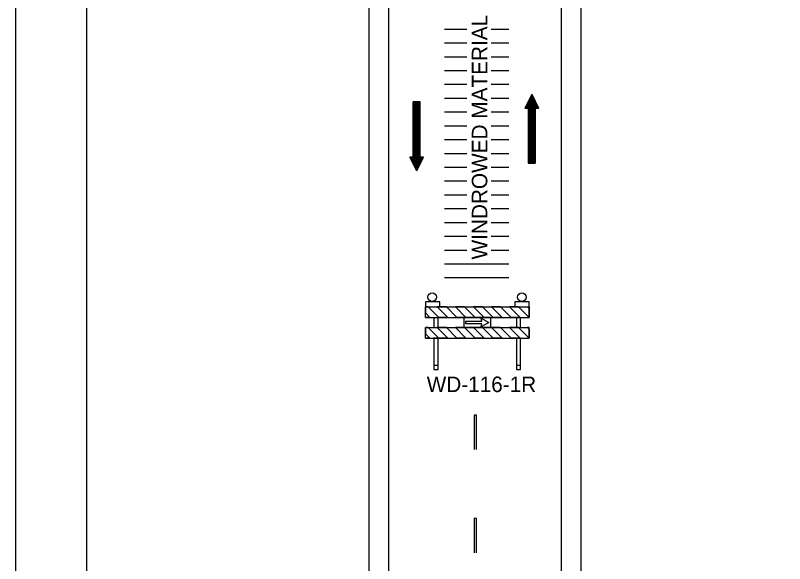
# Model space of a CAD drawing. Extents: x 797 to 1013, y 120 to 399.
# Drawn here: x 797.2 to 905.2, y 193.1 to 270.1 of the extents above; entities that cross this region are included whole.
import ezdxf

# ---------------------------------------------------------------- set-up
doc = ezdxf.new("R2010")
doc.units = 0
for name, color, linetype in [('Level 10', 7, 'Continuous'), ('Level 2', 7, 'Continuous'), ('Level 5', 7, 'Continuous'), ('Level 60', 7, 'Continuous')]:
    doc.layers.add(name, color=color, linetype=linetype)

msp = doc.modelspace()

# ---------------------------------------------------------------- linework, layer by layer
at = {"layer": 'Level 10'}
for p, q in [((846.78, 383.98), (846.78, 135.76)), ((849.54, 383.98), (849.54, 135.76)), ((873.78, 383.98), (873.78, 135.76)), ((876.53, 383.98), (876.53, 135.76)), ((857.39, 268.16), (860.54, 268.16)), ((863.97, 268.16), (866.43, 268.16)), ((857.39, 266.22), (860.54, 266.22)), ((863.97, 266.22), (866.43, 266.22)), ((857.39, 264.28), (860.54, 264.28)), ((863.97, 264.28), (866.43, 264.28)), ((849.54, 262.25), (849.55, 262.24)), ((857.39, 262.34), (860.54, 262.34)), ((863.97, 262.34), (866.43, 262.34)), ((857.39, 260.4), (860.54, 260.4)), ((863.97, 260.4), (866.43, 260.4)), ((857.39, 258.46), (860.54, 258.46)), ((863.97, 258.46), (866.43, 258.46)), ((869.65, 259.01), (868.68, 257.07)), ((869.29, 258.28), (869.29, 249.31)), ((869.41, 258.52), (869.41, 249.31)), ((869.53, 258.77), (869.53, 249.31)), ((869.65, 259.01), (869.65, 249.31)), ((869.65, 259.01), (870.62, 257.07)), ((869.77, 258.77), (869.77, 249.31)), ((869.89, 258.52), (869.89, 249.31)), ((870.01, 258.28), (870.01, 249.31)), ((853.03, 250.17), (853.03, 257.93)), ((854, 257.93), (853.03, 257.93)), ((853.03, 249.2), (853.03, 257.93)), ((853.15, 248.96), (853.15, 257.93)), ((853.27, 248.72), (853.27, 257.93)), ((853.39, 248.47), (853.39, 257.93)), ((853.51, 248.23), (853.51, 257.93)), ((853.63, 248.47), (853.63, 257.93)), ((853.75, 248.72), (853.75, 257.93)), ((853.88, 248.96), (853.88, 257.93)), ((854, 250.17), (854, 257.93)), ((854, 249.2), (854, 257.93)), ((868.68, 257.07), (869.17, 257.07)), ((868.8, 257.31), (868.8, 257.07)), ((868.92, 257.55), (868.92, 257.07)), ((869.05, 257.8), (869.05, 257.07)), ((869.17, 258.04), (869.17, 249.31)), ((869.17, 257.07), (869.17, 249.31)), ((870.14, 258.04), (870.14, 249.31)), ((870.14, 257.07), (870.14, 249.31)), ((870.14, 257.07), (870.62, 257.07)), ((870.26, 257.8), (870.26, 257.07)), ((870.38, 257.55), (870.38, 257.07)), ((870.5, 257.31), (870.5, 257.07)), ((857.39, 256.52), (860.54, 256.52)), ((863.97, 256.52), (866.43, 256.52)), ((857.39, 254.58), (860.54, 254.58)), ((863.97, 254.58), (866.43, 254.58)), ((857.39, 252.64), (860.54, 252.64)), ((863.97, 252.64), (866.43, 252.64)), ((857.39, 250.7), (860.54, 250.7)), ((863.97, 250.7), (866.43, 250.7)), ((853.51, 248.23), (852.54, 250.17)), ((853.03, 250.17), (852.54, 250.17)), ((852.66, 249.93), (852.66, 250.17)), ((852.78, 249.69), (852.78, 250.17)), ((852.9, 249.44), (852.9, 250.17)), ((853.51, 248.23), (854.48, 250.17)), ((854.48, 250.17), (854, 250.17)), ((854.12, 249.44), (854.12, 250.17)), ((854.24, 249.69), (854.24, 250.17)), ((854.36, 249.93), (854.36, 250.17)), ((857.39, 248.76), (860.54, 248.76)), ((863.97, 248.76), (866.43, 248.76)), ((869.17, 249.31), (870.14, 249.31)), ((857.39, 246.83), (860.54, 246.83)), ((863.97, 246.83), (866.43, 246.83)), ((857.39, 244.89), (860.54, 244.89)), ((863.97, 244.89), (866.43, 244.89)), ((857.39, 242.95), (860.54, 242.95)), ((863.97, 242.95), (866.43, 242.95)), ((857.39, 241.01), (860.54, 241.01)), ((863.97, 241.01), (866.43, 241.01)), ((857.39, 239.07), (860.54, 239.07)), ((863.97, 239.07), (866.43, 239.07)), ((857.39, 237.13), (860.54, 237.13)), ((863.97, 237.13), (866.43, 237.13)), ((857.39, 235.19), (866.43, 235.19)), ((857.39, 233.25), (866.43, 233.25)), ((860.18, 226.26), (860.18, 227.64)), ((860.18, 227.64), (863.85, 227.64)), ((860.42, 226.75), (860.42, 227.15)), ((860.42, 227.15), (862.66, 227.15)), ((860.42, 226.75), (860.42, 227.15)), ((860.42, 227.15), (862.66, 227.15)), ((862.66, 227.15), (862.54, 227.56)), ((862.54, 227.56), (863.61, 226.95)), ((862.66, 227.15), (862.54, 227.56)), ((862.54, 227.56), (863.61, 226.95)), ((863.61, 226.95), (862.54, 226.34)), ((863.61, 226.95), (862.54, 226.34)), ((863.85, 227.64), (863.85, 226.26)), ((863.85, 226.26), (860.18, 226.26)), ((862.66, 226.75), (860.42, 226.75)), ((862.66, 226.75), (860.42, 226.75)), ((862.54, 226.34), (862.66, 226.75)), ((862.54, 226.34), (862.66, 226.75))]:
    msp.add_line(p, q, dxfattribs=at)
for points in [[(854.73, 229.15), (856.73, 229.15), (856.73, 229.87), (854.73, 229.87)], [(867.28, 229.15), (869.29, 229.15), (869.29, 229.87), (867.28, 229.87)]]:
    msp.add_lwpolyline(points, close=True, dxfattribs=at)
for centre in [(855.68, 230.52), (868.27, 230.52)]:
    msp.add_circle(centre, 0.606, dxfattribs=at)
at = {"layer": 'Level 2'}
for p, q in [((861.59, 213.94), (861.59, 209.1)), ((861.88, 213.94), (861.59, 213.94)), ((861.88, 209.1), (861.88, 213.94)), ((861.59, 199.42), (861.59, 194.58)), ((861.88, 199.42), (861.59, 199.42)), ((861.88, 194.58), (861.88, 199.42))]:
    msp.add_line(p, q, dxfattribs=at)
at = {"layer": 'Level 5'}
for p, q in [((854.73, 229.15), (869.29, 229.15)), ((854.73, 227.65), (854.73, 229.15)), ((857.11, 229.15), (857.71, 229.15)), ((869.29, 227.65), (869.29, 229.15)), ((854.73, 227.65), (869.29, 227.65)), ((856.51, 227.62), (856.51, 227.65)), ((863.85, 227.64), (860.18, 227.64)), ((863.85, 227.64), (860.18, 227.64)), ((860.42, 226.75), (860.42, 227.15)), ((860.42, 227.15), (862.66, 227.15)), ((862.66, 227.15), (862.54, 227.56)), ((862.54, 227.56), (863.61, 226.95)), ((868.09, 227.62), (868.09, 227.65)), ((854.73, 224.74), (854.73, 226.24)), ((854.73, 226.24), (869.29, 226.24)), ((855.92, 226.24), (856.22, 226.24)), ((860.18, 226.26), (863.85, 226.26)), ((860.18, 226.26), (863.85, 226.26)), ((869.29, 224.74), (869.29, 226.24)), ((854.73, 224.74), (869.29, 224.74)), ((855.92, 220.94), (856.51, 220.94)), ((867.5, 220.94), (868.09, 220.94))]:
    msp.add_line(p, q, dxfattribs=at)
for points in [[(855.13, 229.15), (854.73, 229.15), (854.73, 228.29), (855.36, 227.65), (856.63, 227.65)], [(857.67, 229.15), (856.4, 229.15), (857.89, 227.65), (859.16, 227.65)], [(860.2, 229.15), (858.93, 229.15), (860.42, 227.65), (861.69, 227.65)], [(862.73, 229.15), (861.47, 229.15), (862.96, 227.65), (864.22, 227.65)], [(865.26, 229.15), (864, 229.15), (865.49, 227.65), (866.75, 227.65)], [(867.79, 229.15), (866.53, 229.15), (868.02, 227.65), (869.29, 227.65)], [(869.06, 229.15), (869.29, 229.15), (869.29, 228.92)], [(856.51, 227.62), (855.92, 227.62), (855.92, 226.24), (856.51, 226.24)], [(868.09, 227.62), (867.5, 227.65), (867.5, 226.24), (868.09, 226.24)], [(855.13, 226.24), (854.73, 226.24), (854.73, 225.38), (855.36, 224.74), (856.63, 224.74)], [(857.67, 226.24), (856.4, 226.24), (857.89, 224.74), (859.16, 224.74)], [(860.2, 226.24), (858.93, 226.24), (860.42, 224.74), (861.69, 224.74)], [(862.73, 226.24), (861.47, 226.24), (862.96, 224.74), (864.22, 224.74)], [(865.26, 226.24), (864, 226.24), (865.49, 224.74), (866.75, 224.74)], [(867.79, 226.24), (866.53, 226.24), (868.02, 224.74), (869.29, 224.74)], [(869.29, 226.24), (869.06, 226.24), (869.29, 226.01)], [(856.51, 224.73), (855.92, 224.73), (855.92, 220.34), (856.51, 220.34)], [(868.09, 224.73), (867.5, 224.73), (867.5, 220.34), (868.09, 220.34)]]:
    msp.add_lwpolyline(points, close=True, dxfattribs=at)
for points in [[(855.13, 229.15), (856.4, 229.15), (857.89, 227.65), (856.63, 227.65), (855.13, 229.15)], [(857.67, 229.15), (858.93, 229.15), (860.42, 227.65), (859.16, 227.65), (857.67, 229.15)], [(861.69, 227.65), (860.2, 229.15), (861.47, 229.15), (862.96, 227.65), (861.69, 227.65)], [(864.22, 227.65), (862.73, 229.15), (864, 229.15), (865.49, 227.65), (864.22, 227.65)], [(866.75, 227.65), (865.26, 229.15), (866.53, 229.15), (868.02, 227.65), (866.75, 227.65)], [(869.29, 227.65), (867.79, 229.15), (869.06, 229.15), (869.29, 228.92), (869.29, 227.65)], [(854.73, 228.29), (855.36, 227.65), (854.73, 227.65), (854.73, 228.29)], [(855.13, 226.24), (856.4, 226.24), (857.89, 224.74), (856.63, 224.74), (855.13, 226.24)], [(857.67, 226.24), (858.93, 226.24), (860.42, 224.74), (859.16, 224.74), (857.67, 226.24)], [(861.69, 224.74), (860.2, 226.24), (861.47, 226.24), (862.96, 224.74), (861.69, 224.74)], [(864.22, 224.74), (862.73, 226.24), (864, 226.24), (865.49, 224.74), (864.22, 224.74)], [(866.75, 224.74), (865.26, 226.24), (866.53, 226.24), (868.02, 224.74), (866.75, 224.74)], [(869.29, 224.74), (867.79, 226.24), (869.06, 226.24), (869.29, 226.01), (869.29, 224.74)], [(854.73, 225.38), (855.36, 224.74), (854.73, 224.74), (854.73, 225.38)]]:
    msp.add_lwpolyline(points, dxfattribs=at)
at = {"layer": 'Level 60'}
for points in [[(1013.16, 399.38), (797.16, 399.38), (797.16, 120.38), (1013.16, 120.38)], [(994.03, 388.57), (807.16, 388.57), (807.16, 131.19), (994.03, 131.19)]]:
    msp.add_lwpolyline(points, close=True, dxfattribs=at)

# ---------------------------------------------------------------- texts
at = {"layer": 'Level 10'}
for s, height, rotation, p in [('WINDROWED MATERIAL', 2.1816, 90, (863.42, 235.8)), ('WD-116-1R', 2.177, 360, (854.91, 217.18))]:
    msp.add_text(s, height=height, rotation=rotation, dxfattribs=at).set_placement(p)

doc.saveas('drawing.dxf')
